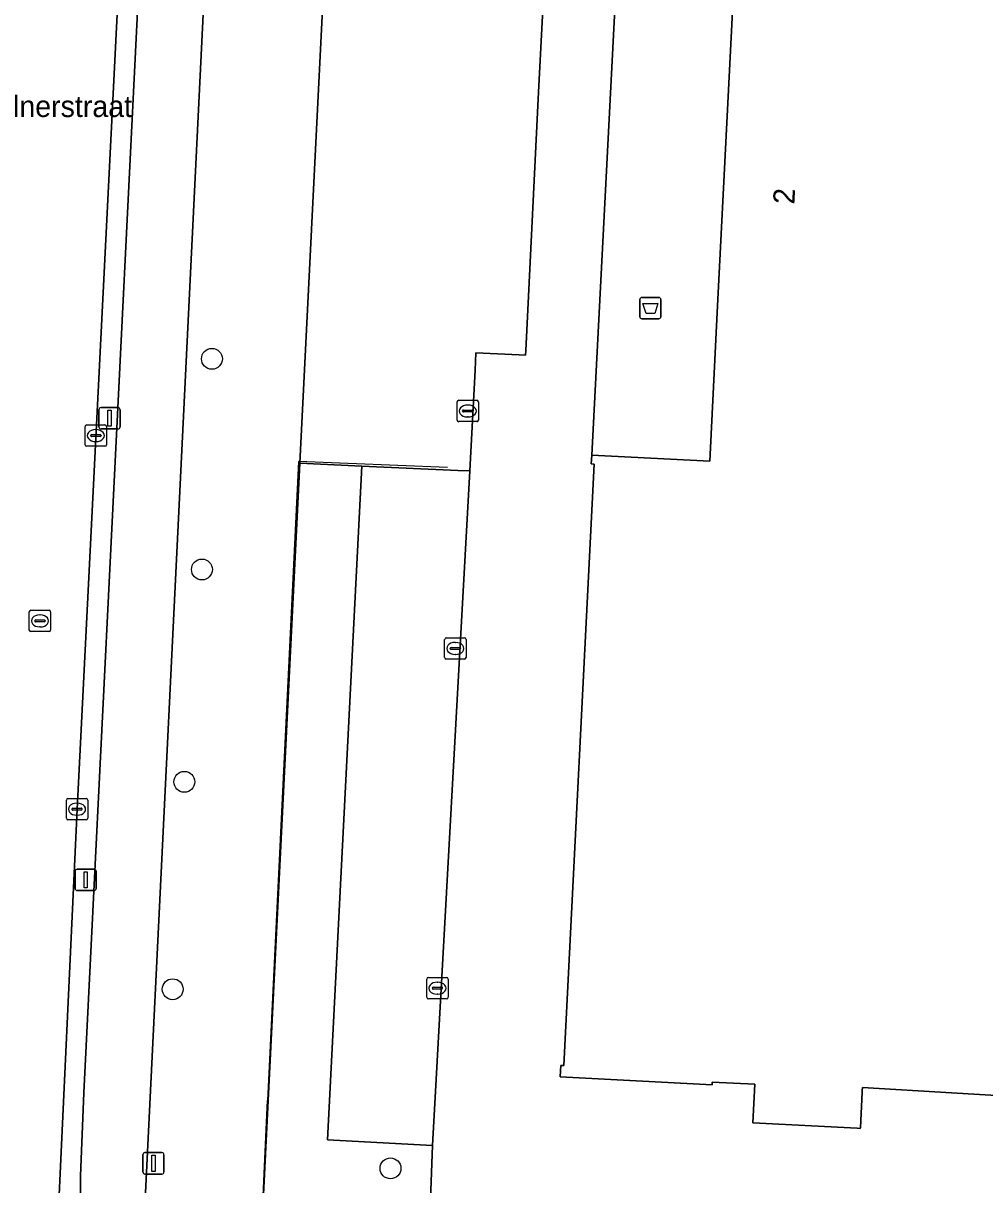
# Model space of a CAD drawing. Extents: x 161758 to 162722, y 384793 to 385405.
# Drawn here: x 162110.4 to 162155.5, y 384894.5 to 384948.9 of the extents above; entities that cross this region are included whole.
import ezdxf

# ---------------------------------------------------------------- set-up
doc = ezdxf.new("R2010")
doc.units = 0
for name, color, linetype in [('IMGEO_Afvalbak', 7, 'Continuous'), ('IMGEO_Berm_groen', 7, 'Continuous'), ('IMGEO_Boom', 7, 'Continuous'), ('IMGEO_Fietspad_gesloten', 7, 'Continuous'), ('IMGEO_Groenvoorziening', 7, 'Continuous'), ('IMGEO_Hek', 7, 'Continuous'), ('IMGEO_Kolk', 7, 'Continuous'), ('IMGEO_Lichtmast', 7, 'Continuous'), ('IMGEO_Openbare_ruimte_label', 7, 'Continuous'), ('IMGEO_Pand', 7, 'Continuous'), ('IMGEO_Pand_nummerreeks', 7, 'Continuous'), ('IMGEO_Parkeervlak_open', 7, 'Continuous'), ('IMGEO_Rijbaan_lokaal_gesloten', 7, 'Continuous'), ('IMGEO_Rijbaan_lokaal_open', 7, 'Continuous'), ('IMGEO_Rioolput', 7, 'Continuous'), ('IMGEO_Verkeersbordpaal', 7, 'Continuous'), ('IMGEO_Verkeerseiland_open', 7, 'Continuous'), ('IMGEO_Voetpad_open', 7, 'Continuous')]:
    doc.layers.add(name, color=color, linetype=linetype)

msp = doc.modelspace()

# ---------------------------------------------------------------- linework, layer by layer
at = {"layer": 'IMGEO_Afvalbak'}
for p, q in [((162139.32, 384935.172), (162139.32, 384935.972)), ((162139.32, 384935.972), (162139.32, 384935.172)), ((162139.42, 384936.072), (162140.21, 384936.072)), ((162140.21, 384936.072), (162139.42, 384936.072)), ((162140.31, 384935.972), (162140.31, 384935.172)), ((162140.31, 384935.172), (162140.31, 384935.972)), ((162140.21, 384935.072), (162139.42, 384935.072)), ((162139.42, 384935.072), (162140.21, 384935.072))]:
    msp.add_line(p, q, dxfattribs=at)
msp.add_lwpolyline([(162139.463, 384935.786), (162140.167, 384935.786), (162140.018, 384935.316), (162139.612, 384935.316), (162139.463, 384935.786)], dxfattribs=at)
for centre, start, end in [((162139.42, 384935.972), 90, 180), ((162139.42, 384935.972), 90, 180), ((162140.21, 384935.972), 0, 90), ((162140.21, 384935.972), 360, 90), ((162139.42, 384935.172), 180, 270), ((162139.42, 384935.172), 180, 270), ((162140.21, 384935.172), 270, 0), ((162140.21, 384935.172), 270, 0)]:
    msp.add_arc(centre, 0.1, start, end, dxfattribs=at)
at = {"layer": 'IMGEO_Berm_groen'}
msp.add_lwpolyline([(162129.138, 384890.64), (162121.541, 384890.934), (162123.403, 384928.319), (162126.113, 384982.723), (162126.452, 384988.892), (162126.369, 384988.897), (162120.83, 384989.204), (162116.127, 384893.203), (162119.041, 384889.827), (162129.04, 384889.175), (162129.111, 384890.233)], close=True, dxfattribs=at)
at = {"layer": 'IMGEO_Boom'}
for centre in [(162119.282, 384933.201), (162118.814, 384923.338), (162117.99, 384913.396), (162117.444, 384903.685), (162127.644, 384895.3)]:
    msp.add_circle(centre, 0.489, dxfattribs=at)
at = {"layer": 'IMGEO_Fietspad_gesloten'}
msp.add_lwpolyline([(162116.103, 384891.116), (162116.127, 384893.203), (162120.83, 384989.204), (162120.938, 384991.307), (162121.233, 384997.569), (162121.539, 385004.086), (162121.676, 385006.932), (162118.683, 385007.076), (162116.503, 384963.282), (162116.239, 384958.276), (162113.284, 384898.832), (162113.123, 384894.953), (162113.167, 384887.939), (162112.494, 384887.839), (162113.04, 384883.744)], dxfattribs=at)
at = {"layer": 'IMGEO_Groenvoorziening'}
msp.add_lwpolyline([(162129.138, 384890.64), (162129.183, 384891.302), (162129.364, 384891.29), (162129.525, 384893.844), (162129.611, 384896.366), (162124.693, 384896.635), (162126.303, 384928.175), (162123.403, 384928.319), (162121.541, 384890.934)], close=True, dxfattribs=at)
at = {"layer": 'IMGEO_Hek'}
for points in [[(162130.312, 384928.119), (162123.33, 384928.385), (162121.879, 384898.481)], [(162129.223, 384890.637), (162121.541, 384890.934), (162121.879, 384898.481)]]:
    msp.add_lwpolyline(points, dxfattribs=at)
at = {"layer": 'IMGEO_Kolk'}
for p, q in [((162130.763, 384930.332), (162130.763, 384931.184)), ((162130.838, 384931.258), (162131.69, 384931.258)), ((162131.251, 384931.038), (162131.276, 384931.038)), ((162131.764, 384931.184), (162131.764, 384930.332)), ((162131.022, 384930.752), (162131.022, 384930.764)), ((162131.46, 384930.715), (162131.062, 384930.715)), ((162131.065, 384930.801), (162131.463, 384930.801)), ((162131.274, 384930.478), (162131.249, 384930.478)), ((162131.506, 384930.764), (162131.506, 384930.752)), ((162113.345, 384929.18), (162113.345, 384930.032)), ((162113.42, 384930.106), (162114.272, 384930.106)), ((162113.833, 384929.886), (162113.858, 384929.886)), ((162114.346, 384930.032), (162114.346, 384929.18)), ((162131.69, 384930.258), (162130.838, 384930.258)), ((162113.604, 384929.6), (162113.604, 384929.612)), ((162114.042, 384929.563), (162113.644, 384929.563)), ((162113.647, 384929.649), (162114.045, 384929.649)), ((162113.856, 384929.326), (162113.831, 384929.326)), ((162114.088, 384929.612), (162114.088, 384929.6)), ((162114.272, 384929.106), (162113.42, 384929.106)), ((162130.181, 384919.215), (162130.181, 384920.067)), ((162130.256, 384920.141), (162131.108, 384920.141)), ((162131.182, 384920.067), (162131.182, 384919.215)), ((162130.44, 384919.635), (162130.44, 384919.647)), ((162130.878, 384919.598), (162130.48, 384919.598)), ((162130.483, 384919.684), (162130.881, 384919.684)), ((162130.669, 384919.921), (162130.694, 384919.921)), ((162130.924, 384919.647), (162130.924, 384919.635)), ((162131.108, 384919.141), (162130.256, 384919.141)), ((162130.692, 384919.361), (162130.667, 384919.361)), ((162112.466, 384911.689), (162112.466, 384912.541)), ((162112.541, 384912.615), (162113.393, 384912.615)), ((162113.467, 384912.541), (162113.467, 384911.689)), ((162112.725, 384912.109), (162112.725, 384912.121)), ((162113.163, 384912.072), (162112.765, 384912.072)), ((162112.768, 384912.158), (162113.166, 384912.158)), ((162112.954, 384912.395), (162112.979, 384912.395)), ((162113.209, 384912.121), (162113.209, 384912.109)), ((162113.393, 384911.615), (162112.541, 384911.615)), ((162112.977, 384911.835), (162112.952, 384911.835)), ((162129.343, 384903.309), (162129.343, 384904.161)), ((162129.418, 384904.235), (162130.27, 384904.235)), ((162129.602, 384903.729), (162129.602, 384903.741)), ((162129.645, 384903.778), (162130.043, 384903.778)), ((162129.831, 384904.015), (162129.856, 384904.015)), ((162130.086, 384903.741), (162130.086, 384903.729)), ((162130.344, 384904.161), (162130.344, 384903.309)), ((162130.27, 384903.235), (162129.418, 384903.235)), ((162130.04, 384903.692), (162129.642, 384903.692)), ((162129.854, 384903.455), (162129.829, 384903.455))]:
    msp.add_line(p, q, dxfattribs=at)
for points in [[(162130.763, 384930.332), (162130.763, 384931.184)], [(162130.838, 384931.258), (162131.69, 384931.258)], [(162131.764, 384931.184), (162131.764, 384930.332)], [(162113.345, 384929.18), (162113.345, 384930.032)], [(162113.42, 384930.106), (162114.272, 384930.106)], [(162114.346, 384930.032), (162114.346, 384929.18)], [(162131.69, 384930.258), (162130.838, 384930.258)], [(162114.272, 384929.106), (162113.42, 384929.106)], [(162130.181, 384919.215), (162130.181, 384920.067)], [(162130.256, 384920.141), (162131.108, 384920.141)], [(162131.182, 384920.067), (162131.182, 384919.215)], [(162131.108, 384919.141), (162130.256, 384919.141)], [(162112.466, 384911.689), (162112.466, 384912.541)], [(162112.541, 384912.615), (162113.393, 384912.615)], [(162113.467, 384912.541), (162113.467, 384911.689)], [(162113.393, 384911.615), (162112.541, 384911.615)], [(162129.343, 384903.309), (162129.343, 384904.161)], [(162129.418, 384904.235), (162130.27, 384904.235)], [(162130.344, 384904.161), (162130.344, 384903.309)], [(162130.27, 384903.235), (162129.418, 384903.235)]]:
    msp.add_lwpolyline(points, dxfattribs=at)
for centre, radius, start, end in [((162130.84, 384931.182), 0.0765, 91.552, 178.448), ((162130.84, 384931.182), 0.0765, 91.552, 178.448), ((162131.688, 384931.182), 0.0765, 1.552, 88.448), ((162131.688, 384931.182), 0.0765, 1.552, 88.448), ((162131.062, 384930.761), 0.0403, 85.8775, 175.7526), ((162131.059, 384930.751), 0.0366, 178.938, 274.7102), ((162131.463, 384930.758), 0.043, 264.8664, 352.4533), ((162131.467, 384930.763), 0.0386, 1.7309, 96.639), ((162113.422, 384930.03), 0.0765, 91.552, 178.448), ((162113.422, 384930.03), 0.0765, 91.552, 178.448), ((162114.27, 384930.03), 0.0765, 1.552, 88.448), ((162114.27, 384930.03), 0.0765, 1.552, 88.448), ((162130.84, 384930.334), 0.0765, 181.552, 268.448), ((162130.84, 384930.334), 0.0765, 181.552, 268.448), ((162131.688, 384930.334), 0.0765, 271.552, 358.448), ((162131.688, 384930.334), 0.0765, 271.552, 358.448), ((162113.644, 384929.609), 0.0403, 85.8775, 175.7526), ((162113.641, 384929.599), 0.0366, 178.938, 274.7102), ((162114.045, 384929.606), 0.043, 264.8664, 352.4533), ((162114.049, 384929.611), 0.0386, 1.7309, 96.639), ((162113.422, 384929.182), 0.0765, 181.552, 268.448), ((162113.422, 384929.182), 0.0765, 181.552, 268.448), ((162114.27, 384929.182), 0.0765, 271.552, 358.448), ((162114.27, 384929.182), 0.0765, 271.552, 358.448), ((162130.258, 384920.065), 0.0765, 91.552, 178.448), ((162130.258, 384920.065), 0.0765, 91.552, 178.448), ((162131.106, 384920.065), 0.0765, 1.552, 88.448), ((162131.106, 384920.065), 0.0765, 1.552, 88.448), ((162130.48, 384919.644), 0.0403, 85.8775, 175.7526), ((162130.477, 384919.634), 0.0366, 178.938, 274.7102), ((162130.881, 384919.641), 0.043, 264.8664, 352.4533), ((162130.885, 384919.646), 0.0386, 1.7309, 96.639), ((162130.258, 384919.217), 0.0765, 181.552, 268.448), ((162130.258, 384919.217), 0.0765, 181.552, 268.448), ((162131.106, 384919.217), 0.0765, 271.552, 358.448), ((162131.106, 384919.217), 0.0765, 271.552, 358.448), ((162112.543, 384912.539), 0.0765, 91.552, 178.448), ((162112.543, 384912.539), 0.0765, 91.552, 178.448), ((162113.391, 384912.539), 0.0765, 1.552, 88.448), ((162113.391, 384912.539), 0.0765, 1.552, 88.448), ((162112.765, 384912.118), 0.0403, 85.8775, 175.7526), ((162112.762, 384912.108), 0.0366, 178.938, 274.7102), ((162113.166, 384912.115), 0.043, 264.8664, 352.4533), ((162113.17, 384912.12), 0.0386, 1.7309, 96.639), ((162112.543, 384911.691), 0.0765, 181.552, 268.448), ((162112.543, 384911.691), 0.0765, 181.552, 268.448), ((162113.391, 384911.691), 0.0765, 271.552, 358.448), ((162113.391, 384911.691), 0.0765, 271.552, 358.448), ((162129.42, 384904.159), 0.0765, 91.552, 178.448), ((162129.42, 384904.159), 0.0765, 91.552, 178.448), ((162129.642, 384903.738), 0.0403, 85.8775, 175.7526), ((162129.639, 384903.728), 0.0366, 178.938, 274.7102), ((162130.043, 384903.735), 0.043, 264.8664, 352.4533), ((162130.047, 384903.74), 0.0386, 1.7309, 96.639), ((162130.268, 384904.159), 0.0765, 1.552, 88.448), ((162130.268, 384904.159), 0.0765, 1.552, 88.448), ((162129.42, 384903.311), 0.0765, 181.552, 268.448), ((162129.42, 384903.311), 0.0765, 181.552, 268.448), ((162130.268, 384903.311), 0.0765, 271.552, 358.448), ((162130.268, 384903.311), 0.0765, 271.552, 358.448)]:
    msp.add_arc(centre, radius, start, end, dxfattribs=at)
for centre, major_axis, ratio, start_param, end_param in [((162131.25, 384930.758), (-0.387, 0.002), 0.722429, 4.712389, 7.853982), ((162131.275, 384930.758), (-0.39, 0.002), 0.717154, 1.570796, 4.712389), ((162113.832, 384929.606), (-0.387, 0.002), 0.722429, 4.712389, 7.853982), ((162113.857, 384929.606), (-0.39, 0.002), 0.717154, 1.570796, 4.712389), ((162130.668, 384919.641), (-0.387, 0.002), 0.722429, 4.712389, 7.853982), ((162130.693, 384919.641), (-0.39, 0.002), 0.717154, 1.570796, 4.712389), ((162112.953, 384912.115), (-0.387, 0.002), 0.722429, 4.712389, 7.853982), ((162112.978, 384912.115), (-0.39, 0.002), 0.717154, 1.570796, 4.712389), ((162129.83, 384903.735), (-0.387, 0.002), 0.722429, 4.712389, 7.853982), ((162129.855, 384903.735), (-0.39, 0.002), 0.717154, 1.570796, 4.712389)]:
    msp.add_ellipse(centre, major_axis=major_axis, ratio=ratio, start_param=start_param, end_param=end_param, dxfattribs=at)
at = {"layer": 'IMGEO_Lichtmast'}
for p, q in [((162114.093, 384930.915), (162114.883, 384930.915)), ((162114.883, 384930.915), (162114.093, 384930.915)), ((162113.993, 384930.015), (162113.993, 384930.815)), ((162113.993, 384930.815), (162113.993, 384930.015)), ((162114.983, 384930.815), (162114.983, 384930.015)), ((162114.983, 384930.015), (162114.983, 384930.815)), ((162114.883, 384929.915), (162114.093, 384929.915)), ((162114.093, 384929.915), (162114.883, 384929.915)), ((162112.873, 384908.406), (162112.873, 384909.206)), ((162112.873, 384909.206), (162112.873, 384908.406)), ((162112.973, 384909.306), (162113.763, 384909.306)), ((162113.763, 384909.306), (162112.973, 384909.306)), ((162113.863, 384909.206), (162113.863, 384908.406)), ((162113.863, 384908.406), (162113.863, 384909.206)), ((162113.763, 384908.306), (162112.973, 384908.306)), ((162112.973, 384908.306), (162113.763, 384908.306))]:
    msp.add_line(p, q, dxfattribs=at)
for points in [[(162114.413, 384930.79), (162114.563, 384930.79), (162114.563, 384930.04), (162114.413, 384930.04), (162114.413, 384930.79)], [(162113.293, 384909.181), (162113.443, 384909.181), (162113.443, 384908.431), (162113.293, 384908.431), (162113.293, 384909.181)]]:
    msp.add_lwpolyline(points, dxfattribs=at)
for centre, start, end in [((162114.093, 384930.815), 90, 180), ((162114.093, 384930.815), 90, 180), ((162114.883, 384930.815), 0, 90), ((162114.883, 384930.815), 360, 90), ((162114.093, 384930.015), 180, 270), ((162114.093, 384930.015), 180, 270), ((162114.883, 384930.015), 270, 0), ((162114.883, 384930.015), 270, 0), ((162112.973, 384909.206), 90, 180), ((162112.973, 384909.206), 90, 180), ((162113.763, 384909.206), 0, 90), ((162113.763, 384909.206), 360, 90), ((162112.973, 384908.406), 180, 270), ((162112.973, 384908.406), 180, 270), ((162113.763, 384908.406), 270, 0), ((162113.763, 384908.406), 270, 0)]:
    msp.add_arc(centre, 0.1, start, end, dxfattribs=at)
at = {"layer": 'IMGEO_Pand'}
msp.add_lwpolyline([(162143.843, 384953.176), (162143.501, 384946.399), (162142.944, 384935.368), (162142.592, 384928.409), (162137.069, 384928.685), (162137.046, 384928.282), (162137.175, 384928.275), (162135.756, 384900.113), (162135.626, 384900.12), (162135.597, 384899.581), (162142.708, 384899.204), (162142.715, 384899.334), (162144.714, 384899.235), (162144.616, 384897.431), (162149.495, 384897.177), (162149.645, 384897.169), (162149.647, 384897.204), (162149.729, 384898.871), (162149.734, 384898.949), (162149.741, 384899.079), (162153.912, 384898.833), (162158.903, 384898.538)], dxfattribs=at)
at = {"layer": 'IMGEO_Parkeervlak_open'}
msp.add_lwpolyline([(162129.611, 384896.366), (162131.352, 384927.951), (162130.802, 384927.968), (162126.303, 384928.175), (162124.693, 384896.635)], close=True, dxfattribs=at)
at = {"layer": 'IMGEO_Rijbaan_lokaal_gesloten'}
msp.add_lwpolyline([(162110.16, 384875.248), (162110.14, 384874.716), (162109.729, 384868.738), (162109.645, 384867.566), (162115.38, 384866.973), (162115.081, 384868.479), (162114.632, 384871.272), (162114.058, 384875.673), (162113.04, 384883.744), (162112.494, 384887.839), (162112.283, 384889.391), (162112.1, 384893.392), (162112.967, 384912.115), (162115.291, 384958.346), (162115.526, 384963.307)], dxfattribs=at)
at = {"layer": 'IMGEO_Rijbaan_lokaal_open'}
for points in [[(162135.188, 384957.302), (162134.57, 384945.679), (162133.982, 384933.595), (162133.971, 384933.373), (162133.673, 384933.388), (162131.646, 384933.486), (162131.603, 384932.665), (162131.352, 384927.951), (162129.611, 384896.366), (162129.525, 384893.844), (162135.549, 384893.474), (162155.58, 384892.46), (162176.021, 384891.303), (162175.797, 384888.879)], [(162158.903, 384898.538), (162153.912, 384898.833), (162149.741, 384899.079), (162149.734, 384898.949), (162149.729, 384898.871), (162149.647, 384897.204), (162149.645, 384897.169), (162149.495, 384897.177), (162144.616, 384897.431), (162144.714, 384899.235), (162142.715, 384899.334), (162142.708, 384899.204), (162135.597, 384899.581), (162135.626, 384900.12), (162135.756, 384900.113), (162137.175, 384928.275), (162137.046, 384928.282), (162137.069, 384928.685), (162138.35, 384953.517)]]:
    msp.add_lwpolyline(points, dxfattribs=at)
at = {"layer": 'IMGEO_Rioolput'}
for p, q in [((162110.728, 384920.504), (162110.728, 384921.356)), ((162110.803, 384921.43), (162111.655, 384921.43)), ((162111.216, 384921.21), (162111.241, 384921.21)), ((162111.729, 384921.356), (162111.729, 384920.504)), ((162110.987, 384920.924), (162110.987, 384920.936)), ((162111.425, 384920.887), (162111.027, 384920.887)), ((162111.03, 384920.973), (162111.428, 384920.973)), ((162111.239, 384920.65), (162111.214, 384920.65)), ((162111.471, 384920.936), (162111.471, 384920.924)), ((162111.655, 384920.43), (162110.803, 384920.43))]:
    msp.add_line(p, q, dxfattribs=at)
for points in [[(162110.728, 384920.504), (162110.728, 384921.356)], [(162110.803, 384921.43), (162111.655, 384921.43)], [(162111.729, 384921.356), (162111.729, 384920.504)], [(162111.655, 384920.43), (162110.803, 384920.43)]]:
    msp.add_lwpolyline(points, dxfattribs=at)
for centre, radius, start, end in [((162110.805, 384921.354), 0.0765, 91.552, 178.448), ((162110.805, 384921.354), 0.0765, 91.552, 178.448), ((162111.653, 384921.354), 0.0765, 1.552, 88.448), ((162111.653, 384921.354), 0.0765, 1.552, 88.448), ((162111.027, 384920.933), 0.0403, 85.8775, 175.7526), ((162111.024, 384920.923), 0.0366, 178.938, 274.7102), ((162111.428, 384920.93), 0.043, 264.8664, 352.4533), ((162111.432, 384920.935), 0.0386, 1.7309, 96.639), ((162110.805, 384920.506), 0.0765, 181.552, 268.448), ((162110.805, 384920.506), 0.0765, 181.552, 268.448), ((162111.653, 384920.506), 0.0765, 271.552, 358.448), ((162111.653, 384920.506), 0.0765, 271.552, 358.448)]:
    msp.add_arc(centre, radius, start, end, dxfattribs=at)
for centre, major_axis, ratio, start_param, end_param in [((162111.215, 384920.93), (-0.387, 0.002), 0.722429, 4.712389, 7.853982), ((162111.24, 384920.93), (-0.39, 0.002), 0.717154, 1.570796, 4.712389)]:
    msp.add_ellipse(centre, major_axis=major_axis, ratio=ratio, start_param=start_param, end_param=end_param, dxfattribs=at)
at = {"layer": 'IMGEO_Verkeersbordpaal'}
for p, q in [((162116.047, 384895.135), (162116.047, 384895.935)), ((162116.047, 384895.935), (162116.047, 384895.135)), ((162116.147, 384896.035), (162116.937, 384896.035)), ((162116.937, 384896.035), (162116.147, 384896.035)), ((162117.037, 384895.935), (162117.037, 384895.135)), ((162117.037, 384895.135), (162117.037, 384895.935)), ((162116.937, 384895.035), (162116.147, 384895.035)), ((162116.147, 384895.035), (162116.937, 384895.035))]:
    msp.add_line(p, q, dxfattribs=at)
msp.add_lwpolyline([(162116.467, 384895.91), (162116.617, 384895.91), (162116.617, 384895.16), (162116.467, 384895.16), (162116.467, 384895.91)], dxfattribs=at)
for centre, start, end in [((162116.147, 384895.935), 90, 180), ((162116.147, 384895.935), 90, 180), ((162116.937, 384895.935), 0, 90), ((162116.937, 384895.935), 360, 90), ((162116.147, 384895.135), 180, 270), ((162116.147, 384895.135), 180, 270), ((162116.937, 384895.135), 270, 0), ((162116.937, 384895.135), 270, 0)]:
    msp.add_arc(centre, 0.1, start, end, dxfattribs=at)
at = {"layer": 'IMGEO_Verkeerseiland_open'}
msp.add_lwpolyline([(162112.494, 384887.839), (162113.167, 384887.939), (162113.123, 384894.953), (162113.284, 384898.832), (162116.239, 384958.276), (162115.291, 384958.346), (162112.967, 384912.115), (162112.1, 384893.392), (162112.283, 384889.391)], close=True, dxfattribs=at)
at = {"layer": 'IMGEO_Voetpad_open'}
msp.add_lwpolyline([(162126.113, 384982.723), (162123.403, 384928.319), (162126.303, 384928.175), (162130.802, 384927.968), (162131.352, 384927.951), (162131.603, 384932.665), (162131.646, 384933.486), (162133.673, 384933.388), (162133.971, 384933.373), (162133.982, 384933.595), (162134.57, 384945.679), (162135.188, 384957.302)], dxfattribs=at)
msp.add_lwpolyline([(162138.35, 384953.517), (162137.069, 384928.685), (162142.592, 384928.409), (162142.944, 384935.368), (162143.501, 384946.399), (162143.843, 384953.176)], close=True, dxfattribs=at)

# ---------------------------------------------------------------- texts
at = {"layer": 'IMGEO_Openbare_ruimte_label'}
msp.add_text('Ds Theodor Fliednerstraat', height=1, dxfattribs=at).set_placement((162100.007, 384944.52))
at = {"layer": 'IMGEO_Pand_nummerreeks'}
msp.add_text('2', height=1, rotation=87.1984, dxfattribs=at).set_placement((162146.557, 384940.417))

doc.saveas('drawing.dxf')
